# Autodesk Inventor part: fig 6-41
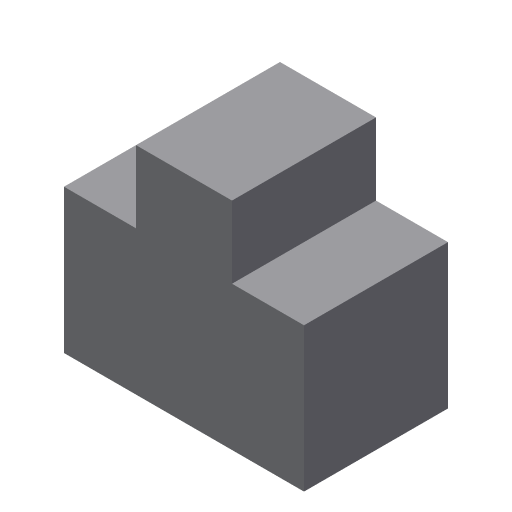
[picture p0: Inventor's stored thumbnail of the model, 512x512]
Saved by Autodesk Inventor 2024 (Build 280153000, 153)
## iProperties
Created: 2005-12
Part Number: fig 6-41
Document SubType Name: Modeling
Designer: CADCIM
Density: 1 g/cm^3
Material: Generic
Appearance: Default
Author: CADCIM
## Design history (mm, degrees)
sketch "Sketch1"
  geometry: L1 (10, 15)-(25, 15); L2 (25, 15)-(25, -15); L3 (25, -15)-(-25, -15); L4 (-25, -15)-(-25, 15); L5 (-25, 15)-(-10, 15); L6 (10, 15)-(10, 30); L7 (10, 30)-(-10, 30); L8 (-10, 30)-(-10, 15)
  constraints: 16 end point, 3 parallel, 3 perpendicular, 2 equal length, 1 collinear, 1 horizontal
  dimensions: "d0" = 50 distance of L2.end L3.end; "d2" = 30 distance of L1.end L2.end; "d3" = 15 distance of L1.start L1.end; "d11" = 15 distance of L7.end L5.end
extrude "Extrusion1" new body sketch "Sketch1" stored distance "d7" = 30; taper "d8" = 0 deg
body "Solid1"
